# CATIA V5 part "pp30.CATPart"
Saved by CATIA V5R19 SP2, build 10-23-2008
Part number: pp30
Publications: "Plane.3"
Bounding box of the stored display mesh (mm): x 10 to 15, y -270.21 to -217.75, z 24.738 to 52.25
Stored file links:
  C:\Users\Welcome\Documents\thinkm2\pp30.CATPart
  C:\Users\Welcome\Documents\thinkm2\Brasmeca.CATProduct
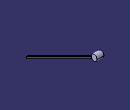
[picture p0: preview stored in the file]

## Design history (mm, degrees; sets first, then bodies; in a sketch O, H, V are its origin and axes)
AxisSystem1: origin (0, 0, 0), X (1, 0, 0), Y (0, 1, 0), Z (0, 0, 1)
Set1
  Plane1: linked copy from another document
  Line1: linked copy from another document
  Plane2: linked copy from another document
  Line2 to Line4: linked copy from another document
  Point1: linked copy from another document
Body1 (main body)
  Sketch1 on Plane2, origin (15, 0, 0), H (0, 1, 0), V (0, 0, 1)
    circle A1 centre (-220, 50) radius 2.25
    reference projected point E1 (-220, 50) from Line2
    radius A1 = 2.25
    distance A1 E1 = 2.25
  Pad1: profile Sketch1, direction (-1, 0, 0), length 5
  Plane3: type Normal, Curve Line3, RefPoint Point1
  Sketch2 on Plane3, origin (0, -206, -103), H (1, 0, 0), V (0, -0.4472, 0.8944)
    line L1 (14.9255, 143.577) -> (13.2595, 143.577)
    line L2 (13.2595, 143.577) -> (13.2595, 142.815)
    line L3 (13.2595, 142.815) -> (14.9255, 142.815)
    line L4 (14.9255, 142.815) -> (14.9255, 143.577)
  Pad2: profile Sketch2, direction (0, 0.8944, 0.4472), length 57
